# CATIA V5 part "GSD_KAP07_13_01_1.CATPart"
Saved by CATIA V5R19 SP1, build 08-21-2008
Part number: GSD_NEAR_01
Definition: Beispielmodell für die Funktion Nahe / Near.
Description: CATIA V5 Flächenmodellierung  Copyright 2009 Maik Hertha IT Consultants
Bounding box of the stored display mesh (mm): x -118.392 to 45.702, y 19.124 to 80.975, z 13.956 to 57.238
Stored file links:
  \GSD_BUCH_UEBUNG\GSD_KAP07_13_01_1.CATPart
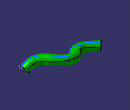
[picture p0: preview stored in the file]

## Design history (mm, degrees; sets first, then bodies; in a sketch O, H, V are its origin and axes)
AxisSystem1 "Absolute Axis System": origin (0, 0, 0), X (1, 0, 0), Y (0, 1, 0), Z (0, 0, 1)
Set1 "Near Support"
  Plane1: type Equation, A 0, B 1, C 0, Length -20
  Point1: type OnPlane, Support Plane1, Direction (-1, 0, 0), H -20, V 20
  Plane2: type Equation, A 0, B 0, C 1, Length -20
  Sketch1 on Plane1, origin (20, -20, 20), H (-1, 0, 0), V (0, 0, 1)
    spline S1 through (-28.6222, 7.5739) (16.6598, 27.2154) (74.1032, 14.2934) (131.2878, 3.9557)
  Sketch2 on Plane2, origin (20, -20, -20), H (1, 0, 0), V (0, 1, 0)
    spline S1 through (-139.2371, 93.2107) (-123.9174, 75.5754) (-83.9302, 69.0919) (-67.5719, 84.3931) (-34.0762, 87.2458) (-10.9667, 62.6083) (19.9324, 49.1226)
  Combine1: Curve1 Sketch1, Curve2 Sketch2
  Sweep1: type Circle, Guide Combine1, Radius 10
Set2 "Near with Extremum"
  DatumSurface1: linked copy from another document
  ReflectLine1 "Reflect line.1": Support DatumSurface1, Angle 6, Direction (0, 0, 1)
  Extremum1 "Extremum.1": Reference DatumSurface1, Direction2 (0, 0, 1), Direction3 (0, 0, 1), Direction (0, 1, 0)
  Near1 "Near.1": ReferenceElement Extremum1, MultiElement ReflectLine1
Body1 (main body)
